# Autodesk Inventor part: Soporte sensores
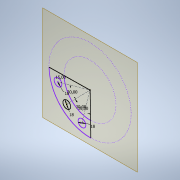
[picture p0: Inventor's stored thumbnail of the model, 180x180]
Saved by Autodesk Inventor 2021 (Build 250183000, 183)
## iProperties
Created: 2021-03
Part Number: Soporte sensores
Material: Genérico
Document SubType Name: Modeling
Designer: ATOUZA
Density: 1 g/cm^3
Appearance: Valor por defecto
Author: ATOUZA
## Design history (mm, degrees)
node "Plano de trabajo1"
sketch "Boceto1"
  geometry: L1 (-29.4, -55.479)-(-54.533, -31.12) reference; L2 (-78.892, -56.253)-(-53.759, -80.612) reference; L3 (0, 0)-(-54.146, -55.866); L4 (0, 0)-(-18.974, -75.514); L5 (0, 0)-(-74.556, -21.232); L6 (0, 0)-(-95.288, -1.49); L7 (0, 0)-(1.49, -95.288); L8 (-88.281, -84.164)-(-87.637, -83.606) reference; L9 (-87.223, -81.124)-(-87.653, -80.388) reference; L10 (-86.41, -79.502)-(-85.857, -80.148) reference; L11 (-83.375, -80.561)-(-82.642, -80.129) reference; L12 (-81.755, -81.37)-(-82.399, -81.927) reference; L13 (-82.813, -84.41)-(-82.383, -85.146) reference; L14 (-83.625, -86.032)-(-84.179, -85.386) reference; L15 (-86.661, -84.972)-(-87.393, -85.405) reference; L16 (-83.338, -78.485)-(-81.09, -78.859) reference; L17 (-84.256, -78.8)-(-83.441, -78.495) reference; L18 (-85.125, -78.214)-(-84.453, -78.767) reference; L19 (-87.467, -77.797)-(-85.219, -78.171) reference; L20 (-89.656, -74.985)-(-87.792, -77.595) reference; L21 (-89.622, -73.89)-(-89.743, -74.612) reference; L22 (-87.173, -73.791)-(-89.047, -73.479) reference; L23 (-86.548, -73.084)-(-86.597, -73.38) reference; L24 (-87.058, -72.796)-(-86.713, -72.854) reference; L25 (-87.008, -72.5)-(-87.058, -72.796) reference; L26 (-91.76, -71.506)-(-87.173, -72.27) reference; L27 (-94.25, -77.326)-(-93.486, -72.74) reference; L28 (-93.789, -77.606)-(-94.085, -77.557) reference; L29 (-93.847, -77.951)-(-93.789, -77.606) reference; L30 (-93.386, -78.231)-(-93.682, -78.181) reference; L31 (-92.499, -75.945)-(-92.811, -77.819) reference; L32 (-91.201, -75.655)-(-91.924, -75.534) reference; L33 (-89.012, -78.467)-(-90.877, -75.857) reference; L34 (-89.3, -81.087)-(-88.926, -78.839) reference; L35 (-88.985, -82.005)-(-89.29, -81.19) reference; L36 (-89.571, -82.874)-(-89.018, -82.202) reference; L37 (-89.988, -85.216)-(-89.613, -82.968) reference; L38 (-92.8, -87.405)-(-90.19, -85.541) reference; L39 (-93.895, -87.371)-(-93.173, -87.491) reference; L40 (-93.994, -84.922)-(-94.306, -86.796) reference; L41 (-94.701, -84.297)-(-94.405, -84.346) reference; L42 (-94.988, -84.807)-(-94.931, -84.461) reference; L43 (-95.284, -84.757)-(-94.988, -84.807) reference; L44 (-96.278, -89.509)-(-95.515, -84.922) reference; L45 (-90.458, -91.999)-(-95.045, -91.235) reference; L46 (-90.179, -91.538)-(-90.228, -91.834) reference; L47 (-89.834, -91.596)-(-90.179, -91.538) reference; L48 (-89.554, -91.135)-(-89.604, -91.431) reference; L49 (-91.84, -90.248)-(-89.965, -90.56) reference; L50 (-92.13, -88.95)-(-92.251, -89.673) reference; L51 (-89.318, -86.761)-(-91.928, -88.626) reference; L52 (-86.698, -87.049)-(-88.945, -86.675) reference; L53 (-85.78, -86.734)-(-86.595, -87.039) reference; L54 (-84.911, -87.32)-(-85.583, -86.767) reference; L55 (-82.569, -87.737)-(-84.817, -87.362) reference; L56 (-80.38, -90.549)-(-82.244, -87.939) reference; L57 (-80.414, -91.644)-(-80.293, -90.922) reference; L58 (-82.863, -91.743)-(-80.989, -92.055) reference; L59 (-83.488, -92.45)-(-83.438, -92.154) reference; L60 (-82.978, -92.737)-(-83.323, -92.68) reference; L61 (-83.027, -93.033)-(-82.978, -92.737) reference; L62 (-78.276, -94.027)-(-82.863, -93.263) reference; L63 (-75.786, -88.207)-(-76.55, -92.794) reference; L64 (-76.247, -87.928)-(-75.951, -87.977) reference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; C1 r 2 at (-54.146, -55.866) reference; C2 r 9 at (-54.146, -55.866); C3 r 9 at (-18.974, -75.514); C4 r 9 at (-74.556, -21.232); C5 r 9 at (-54.146, -55.866); C6 r 9 at (-18.974, -75.514); C7 r 2.75 at (-109.382, -78.709); C8 r 2.75 at (-80.96, -58.402); C9 r 2.75 at (-89.075, -107.131); C10 r 2.75 at (-89.075, -107.131); C11 r 2.75 at (-109.382, -78.709); C12 r 2.75 at (-80.96, -58.402); A1 r 60.3 centre (0, 0) between (-60.293, -0.943) and (0.943, -60.293); A2 r 95.3 centre (0, 0) between (-69.394, -65.319) and (-79.682, -52.277); A3 r 60.3 centre (0, 0) between (-60.293, -0.943) and (0.943, -60.293); A4 r 2.75 centre (-85.018, -82.767) between (-87.223, -81.124) and (-87.637, -83.606) reference; A5 r 3.55 centre (-85.018, -82.767) between (-86.41, -79.502) and (-87.653, -80.388) reference; A6 r 2.75 centre (-85.018, -82.767) between (-83.375, -80.561) and (-85.857, -80.148) reference; A7 r 3.55 centre (-85.018, -82.767) between (-81.755, -81.37) and (-82.642, -80.129) reference; A8 r 2.75 centre (-85.018, -82.767) between (-82.813, -84.41) and (-82.399, -81.927) reference; A9 r 3.55 centre (-85.018, -82.767) between (-83.625, -86.032) and (-82.383, -85.146) reference; A10 r 2.75 centre (-85.018, -82.767) between (-86.661, -84.972) and (-84.179, -85.386) reference; A11 r 3.55 centre (-85.018, -82.767) between (-88.281, -84.164) and (-87.393, -85.405) reference; A12 r 0.2 centre (-84.326, -78.613) between (-84.453, -78.767) and (-84.256, -78.8) reference; A13 r 0.2 centre (-85.252, -78.369) between (-85.125, -78.214) and (-85.219, -78.171) reference; A14 r 0.5 centre (-87.385, -77.304) between (-87.792, -77.595) and (-87.467, -77.797) reference; A15 r 0.5 centre (-89.249, -74.694) between (-89.743, -74.612) and (-89.656, -74.985) reference; A16 r 0.5 centre (-89.129, -73.972) between (-89.047, -73.479) and (-89.622, -73.89) reference; A17 r 0.5 centre (-87.091, -73.298) between (-87.173, -73.791) and (-86.597, -73.38) reference; A18 r 0.2 centre (-86.745, -73.051) between (-86.548, -73.084) and (-86.713, -72.854) reference; A19 r 0.2 centre (-87.206, -72.468) between (-87.008, -72.5) and (-87.173, -72.27) reference; A20 r 1.5 centre (-92.006, -72.986) between (-91.76, -71.506) and (-93.486, -72.74) reference; A21 r 0.2 centre (-94.052, -77.359) between (-94.25, -77.326) and (-94.085, -77.557) reference; A22 r 0.2 centre (-93.65, -77.984) between (-93.847, -77.951) and (-93.682, -78.181) reference; A23 r 0.5 centre (-93.304, -77.737) between (-93.386, -78.231) and (-92.811, -77.819) reference; A24 r 0.5 centre (-92.006, -76.027) between (-91.924, -75.534) and (-92.499, -75.945) reference; A25 r 0.5 centre (-91.283, -76.148) between (-90.877, -75.857) and (-91.201, -75.655) reference; A26 r 0.5 centre (-89.419, -78.757) between (-88.926, -78.839) and (-89.012, -78.467) reference; A27 r 0.2 centre (-89.103, -81.12) between (-89.3, -81.087) and (-89.29, -81.19) reference; A28 r 0.2 centre (-89.172, -82.075) between (-89.018, -82.202) and (-88.985, -82.005) reference; A29 r 0.5 centre (-90.481, -85.134) between (-90.19, -85.541) and (-89.988, -85.216) reference; A30 r 0.5 centre (-93.09, -86.998) between (-93.173, -87.491) and (-92.8, -87.405) reference; A31 r 0.5 centre (-93.813, -86.878) between (-94.306, -86.796) and (-93.895, -87.371) reference; A32 r 0.5 centre (-94.487, -84.84) between (-93.994, -84.922) and (-94.405, -84.346) reference; A33 r 0.2 centre (-94.734, -84.494) between (-94.701, -84.297) and (-94.931, -84.461) reference; A34 r 0.2 centre (-95.317, -84.955) between (-95.284, -84.757) and (-95.515, -84.922) reference; A35 r 1.5 centre (-94.799, -89.755) between (-96.278, -89.509) and (-95.045, -91.235) reference; A36 r 0.2 centre (-90.426, -91.801) between (-90.458, -91.999) and (-90.228, -91.834) reference; A37 r 0.2 centre (-89.801, -91.398) between (-89.834, -91.596) and (-89.604, -91.431) reference; A38 r 0.5 centre (-90.047, -91.053) between (-89.554, -91.135) and (-89.965, -90.56) reference; A39 r 0.5 centre (-91.757, -89.755) between (-92.251, -89.673) and (-91.84, -90.248) reference; A40 r 0.5 centre (-91.637, -89.032) between (-91.928, -88.626) and (-92.13, -88.95) reference; A41 r 0.5 centre (-89.028, -87.168) between (-88.945, -86.675) and (-89.318, -86.761) reference; A42 r 0.2 centre (-86.665, -86.852) between (-86.698, -87.049) and (-86.595, -87.039) reference; A43 r 0.2 centre (-85.71, -86.921) between (-85.583, -86.767) and (-85.78, -86.734) reference; A44 r 0.2 centre (-84.784, -87.165) between (-84.911, -87.32) and (-84.817, -87.362) reference; A45 r 0.5 centre (-82.651, -88.23) between (-82.244, -87.939) and (-82.569, -87.737) reference; A46 r 0.5 centre (-80.787, -90.839) between (-80.293, -90.922) and (-80.38, -90.549) reference; A47 r 0.5 centre (-80.907, -91.562) between (-80.989, -92.055) and (-80.414, -91.644) reference; A48 r 0.5 centre (-82.945, -92.236) between (-82.863, -91.743) and (-83.438, -92.154) reference; A49 r 0.2 centre (-83.29, -92.483) between (-83.488, -92.45) and (-83.323, -92.68) reference; A50 r 0.2 centre (-82.83, -93.066) between (-83.027, -93.033) and (-82.863, -93.263) reference; A51 r 1.5 centre (-78.03, -92.548) between (-78.276, -94.027) and (-76.55, -92.794) reference; A52 r 0.2 centre (-75.984, -88.174) between (-75.786, -88.207) and (-75.951, -87.977) reference; A53 r 0.2 centre (-76.386, -87.55) between (-76.189, -87.583) and (-76.354, -87.353) reference; A54 r 0.5 centre (-76.732, -87.796) between (-76.649, -87.303) and (-77.225, -87.714) reference; A55 r 0.5 centre (-78.03, -89.506) between (-78.112, -90) and (-77.537, -89.588) reference; A56 r 0.5 centre (-78.752, -89.386) between (-79.159, -89.677) and (-78.835, -89.879) reference; A57 r 0.5 centre (-80.617, -86.777) between (-81.11, -86.694) and (-81.024, -87.067) reference; A58 r 0.2 centre (-80.933, -84.414) between (-80.736, -84.447) and (-80.746, -84.344) reference; A59 r 0.2 centre (-80.864, -83.459) between (-81.018, -83.332) and (-81.051, -83.529) reference; A60 r 0.2 centre (-80.62, -82.533) between (-80.465, -82.66) and (-80.422, -82.565) reference; A61 r 0.5 centre (-79.555, -80.4) between (-79.846, -79.993) and (-80.048, -80.318) reference; A62 r 0.5 centre (-76.945, -78.535) between (-76.863, -78.042) and (-77.236, -78.129) reference; A63 r 0.5 centre (-76.223, -78.656) between (-75.73, -78.738) and (-76.141, -78.163) reference; A64 r 0.5 centre (-75.549, -80.694) between (-76.042, -80.612) and (-75.631, -81.187) reference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; 2 further points
  constraints: 40 end point, 18 centre point, 17 coincident, 17 point on circle, 6 midpoint, 5 point on line, 4 concentric, 3 parallel, 2 collinear, 2 perpendicular
  dimensions: "d0" = 18 diameter of C2; "d1" = 30 deg angle of L4 L3; "d2" = 18 diameter of C3; "d3" = 30 deg angle of L3 L5; "d4" = 18 diameter of C4; "d6" = 15 deg angle of L6 L5; "d7" = 15 deg angle of L7 L4; "d8" = 21 distance between parallel lines of L90 L88; "d9" = 21 distance between parallel lines of L91 L89; "d10" = 10 deg angle of L94 L95; "d12" = 150 radius of A74; "d14" = 10 deg angle of L96 L94; "d16" = 14.2 distance of L97.start L97.end; "d18" = 14.2 distance of L98.start L98.end; "d19" = 14.2 distance of L99.start L99.end; "d20" = 14.2 distance of L100.start L100.end; "d21" = 5.5 diameter of C7; "d22" = 5.5 diameter of C8; "d23" = 5.5 diameter of C9
extrude "Extrusión1" new body sketch "Boceto1" distance "d24" = 5.5; taper "d25" = 0 deg
node "Sólido1"
node "Referencia1"
node "Referencia2"
node "Referencia3"
node "Referencia4"
